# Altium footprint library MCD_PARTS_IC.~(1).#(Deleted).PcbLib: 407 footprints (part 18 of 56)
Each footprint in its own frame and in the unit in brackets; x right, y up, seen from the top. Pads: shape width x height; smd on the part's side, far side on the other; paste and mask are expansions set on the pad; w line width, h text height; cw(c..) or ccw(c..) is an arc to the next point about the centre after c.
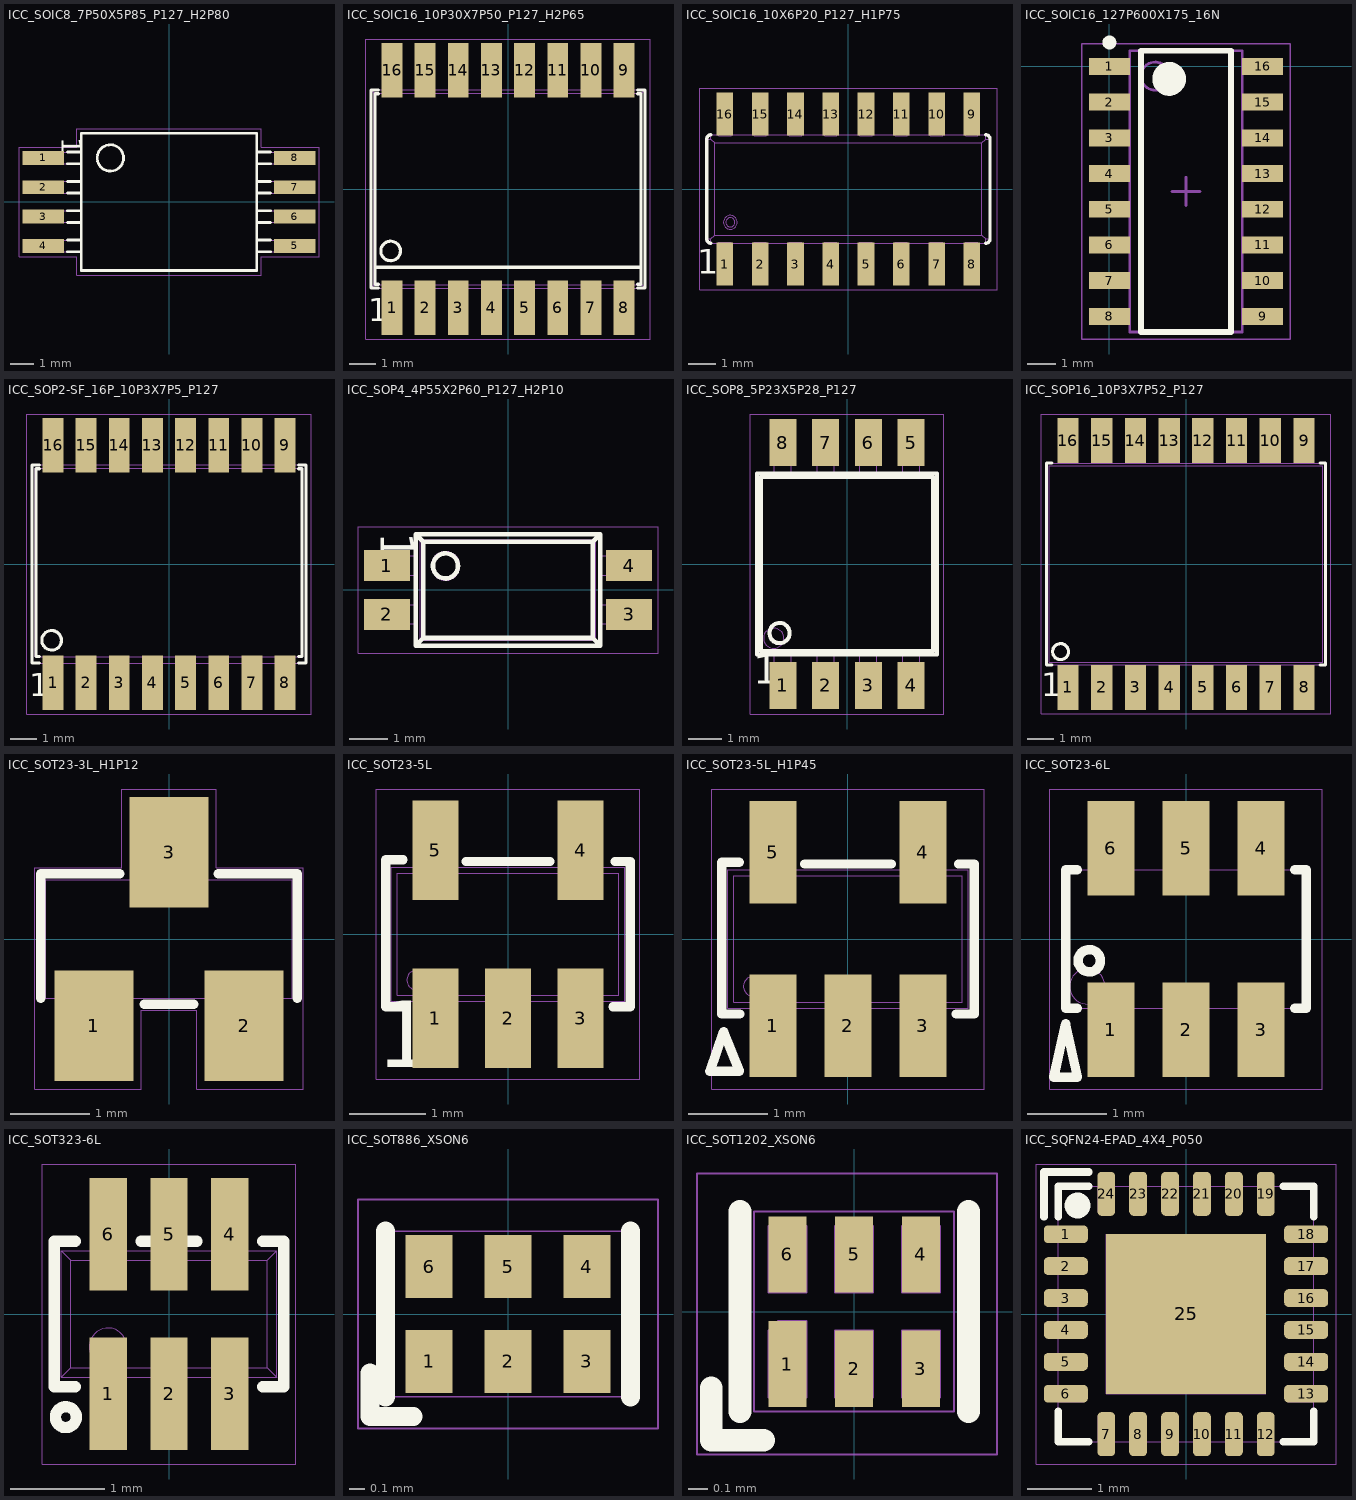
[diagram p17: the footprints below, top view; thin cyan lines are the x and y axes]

## ICC_SOIC8_7P50X5P85_P127_H2P80 [mm] "MCD-02031"
height 2.8
pads (8):
  rect 1.8x0.6 smd mask+0.05: 1(-5.45,1.905) 2(-5.45,0.635) 3(-5.45,-0.635) 4(-5.45,-1.905) 5(5.45,-1.905) 6(5.45,-0.635) 7(5.45,0.635) 8(5.45,1.905)
Top Overlay:
  circle w0.12: c-2.54,1.905 r0.572
  lines w0.12: -4.4,-2.159 -3.8,-2.159 ; -4.4,-1.651 -3.8,-1.651 ; -4.4,-0.889 -3.8,-0.889 ; -4.4,-0.381 -3.8,-0.381 ; -4.4,0.381 -3.8,0.381 ; -4.4,0.889 -3.8,0.889 ; -4.4,1.651 -3.8,1.651 ; -4.4,2.159 -3.8,2.159 ; 3.8,-2.159 4.4,-2.159 ; 3.8,-1.651 4.4,-1.651 ; 3.8,-0.889 4.4,-0.889 ; 3.8,-0.381 4.4,-0.381 ; 3.8,0.381 4.4,0.381 ; 3.8,0.889 4.4,0.889 ; 3.8,1.651 4.4,1.651 ; 3.8,2.159 4.4,2.159 ; -3.8,-2.975 -3.8,2.975 3.8,2.975 3.8,-2.975 -3.8,-2.975
  text "1" at -4.953,2.794 h1.5
M14-Top Assembly:
  circle w0.01: c-2.54,1.905 r0.572
  lines w0.01: -4.801,-2.159 -4.801,-1.651 ; -4.801,-0.889 -4.801,-0.381 ; -4.801,0.381 -4.801,0.889 ; -4.801,1.651 -4.801,2.159 ; -3.8,-2.159 -5.875,-2.159 -5.875,-1.651 -3.8,-1.651 ; -3.8,-0.889 -5.875,-0.889 -5.875,-0.381 -3.8,-0.381 ; -3.8,0.381 -5.875,0.381 -5.875,0.889 -3.8,0.889 ; -3.8,1.651 -5.875,1.651 -5.875,2.159 -3.8,2.159 ; 3.8,-2.159 5.875,-2.159 5.875,-1.651 3.8,-1.651 ; 3.8,-0.889 5.875,-0.889 5.875,-0.381 3.8,-0.381 ; 3.8,0.381 5.875,0.381 5.875,0.889 3.8,0.889 ; 3.8,1.651 5.875,1.651 5.875,2.159 3.8,2.159 ; 4.801,-2.159 4.801,-1.651 ; 4.801,-0.889 4.801,-0.381 ; 4.801,0.381 4.801,0.889 ; 4.801,1.651 4.801,2.159 ; -3.8,-2.975 3.8,-2.975 3.8,2.975 -3.8,2.975 -3.8,-2.975
  text "1" at -5.45,1.655 h0.75
  text "4" at -5.475,-2.145 h0.75
  text "5" at 5.149,-2.132 h0.75
  text "8" at 5.149,1.668 h0.75
  text "'.Designator'" at -2,-0.5 h0.75
M16-Top Courtyard:
  lines w0.01: -6.5,-2.375 -6.5,2.375 -4,2.375 -4,3.175 -3.8,3.175 4,3.175 4,2.375 6.5,2.375 6.5,-2.375 4,-2.375 4,-3.175 -4,-3.175 -4,-2.375 -6.5,-2.375
3D body: height 2.81, standoff 2.8, extent -3.046,1.401 -2.05,2.399
3D body: height 2.8, standoff 0, extent -3.8,-2.975 3.8,2.975
3D body: height 1.65, standoff 1.4, extent -5.05,1.651 -3.8,2.159
3D body: height 0.25, standoff 0, extent -5.875,1.651 -4.801,2.159
3D body: height 1.65, standoff 0, extent -5.05,1.651 -4.801,2.159
3D body: height 1.65, standoff 0, extent -5.05,0.381 -4.801,0.889
3D body: height 0.25, standoff 0, extent -5.875,0.381 -4.801,0.889
3D body: height 1.65, standoff 1.4, extent -5.05,0.381 -3.8,0.889
3D body: height 1.65, standoff 0, extent -5.05,-0.889 -4.801,-0.381
3D body: height 0.25, standoff 0, extent -5.875,-0.889 -4.801,-0.381
3D body: height 1.65, standoff 1.4, extent -5.05,-0.889 -3.8,-0.381
3D body: height 1.65, standoff 0, extent -5.05,-2.159 -4.801,-1.651
3D body: height 0.25, standoff 0, extent -5.875,-2.159 -4.801,-1.651
3D body: height 1.65, standoff 1.4, extent -5.05,-2.159 -3.8,-1.651
3D body: height 1.65, standoff 0, extent 4.801,-2.159 5.05,-1.651
3D body: height 0.25, standoff 0, extent 4.801,-2.159 5.875,-1.651
3D body: height 1.65, standoff 1.4, extent 3.8,-2.159 5.05,-1.651
3D body: height 1.65, standoff 0, extent 4.801,-0.889 5.05,-0.381
3D body: height 0.25, standoff 0, extent 4.801,-0.889 5.875,-0.381
3D body: height 1.65, standoff 1.4, extent 3.8,-0.889 5.05,-0.381
3D body: height 1.65, standoff 0, extent 4.801,0.381 5.05,0.889
3D body: height 0.25, standoff 0, extent 4.801,0.381 5.875,0.889
3D body: height 1.65, standoff 1.4, extent 3.8,0.381 5.05,0.889
3D body: height 1.65, standoff 0, extent 4.801,1.651 5.05,2.159
3D body: height 0.25, standoff 0, extent 4.801,1.651 5.875,2.159
3D body: height 1.65, standoff 1.4, extent 3.8,1.651 5.05,2.159

## ICC_SOIC16_10P30X7P50_P127_H2P65 [mm] "MCD-02008"
height 2.65
pads (16):
  rect 0.8x2.1 smd mask+0.05: 1(-4.445,-4.55) 2(-3.175,-4.55) 3(-1.905,-4.55) 4(-0.635,-4.55) 5(0.635,-4.55) 6(1.905,-4.55) 7(3.175,-4.55) 8(4.445,-4.55) 9(4.445,4.55) 10(3.175,4.55) 11(1.905,4.55) 12(0.635,4.55) 13(-0.635,4.55) 14(-1.905,4.55) 15(-3.175,4.55) 16(-4.445,4.55)
Top Overlay:
  circle w0.12: c-4.5,-2.375 r0.375
  lines w0.12: -5.1,-3 5.1,-3 ; -4.975,-3.8 -5.25,-3.8 -5.25,3.8 -4.975,3.8 ; -4.975,-3.65 -5.1,-3.65 -5.1,3.65 -4.975,3.65 ; 4.975,-3.8 5.25,-3.8 5.25,3.8 4.975,3.8 ; 4.975,-3.65 5.1,-3.65 5.1,3.65 4.975,3.65
  text "1" at -5.35,-5.35 h1.5
M14-Top Assembly:
  circle w0.01: c-4.5,-2.375 r0.378
  lines w0.01: -5.125,-3 5.125,-3 ; -4.699,-4.45 -4.191,-4.45 ; -4.699,-4.15 -4.191,-4.15 ; -4.699,-3.8 -4.699,-5.35 -4.191,-5.35 -4.191,-3.8 ; -4.699,3.8 -4.699,5.35 -4.191,5.35 -4.191,3.8 ; -4.699,4.15 -4.191,4.15 ; -4.699,4.45 -4.191,4.45 ; -3.429,-4.45 -2.921,-4.45 ; -3.429,-4.15 -2.921,-4.15 ; -3.429,-3.8 -3.429,-5.35 -2.921,-5.35 -2.921,-3.8 ; -3.429,3.8 -3.429,5.35 -2.921,5.35 -2.921,3.8 ; -3.429,4.15 -2.921,4.15 ; -3.429,4.45 -2.921,4.45 ; -2.159,-4.45 -1.651,-4.45 ; -2.159,-4.15 -1.651,-4.15 ; -2.159,-3.8 -2.159,-5.35 -1.651,-5.35 -1.651,-3.8 ; -2.159,3.8 -2.159,5.35 -1.651,5.35 -1.651,3.8 ; -2.159,4.15 -1.651,4.15 ; -2.159,4.45 -1.651,4.45 ; -0.889,-4.45 -0.381,-4.45 ; -0.889,-4.15 -0.381,-4.15 ; -0.889,-3.8 -0.889,-5.35 -0.381,-5.35 -0.381,-3.8 ; -0.889,3.8 -0.889,5.35 -0.381,5.35 -0.381,3.8 ; -0.889,4.15 -0.381,4.15 ; -0.889,4.45 -0.381,4.45 ; 0.381,-4.45 0.889,-4.45 ; 0.381,-4.15 0.889,-4.15 ; 0.381,-3.8 0.381,-5.35 0.889,-5.35 0.889,-3.8 ; 0.381,3.8 0.381,5.35 0.889,5.35 0.889,3.8 ; 0.381,4.15 0.889,4.15 ; 0.381,4.45 0.889,4.45 ; 1.651,-4.45 2.159,-4.45 ; 1.651,-4.15 2.159,-4.15 ; 1.651,-3.8 1.651,-5.35 2.159,-5.35 2.159,-3.8 ; 1.651,3.8 1.651,5.35 2.159,5.35 2.159,3.8 ; 1.651,4.15 2.159,4.15 ; 1.651,4.45 2.159,4.45 ; 2.921,-4.45 3.429,-4.45 ; 2.921,-4.15 3.429,-4.15 ; 2.921,-3.8 2.921,-5.35 3.429,-5.35 3.429,-3.8 ; 2.921,3.8 2.921,5.35 3.429,5.35 3.429,3.8 ; 2.921,4.15 3.429,4.15 ; 2.921,4.45 3.429,4.45 ; 4.191,-4.45 4.699,-4.45 ; 4.191,-4.15 4.699,-4.15 ; 4.191,-3.8 4.191,-5.35 4.699,-5.35 4.699,-3.8 ; 4.191,3.8 4.191,5.35 4.699,5.35 4.699,3.8 ; 4.191,4.15 4.699,4.15 ; 4.191,4.45 4.699,4.45 ; -5.25,-3.8 5.25,-3.8 ; -5.25,-3.8 -5.25,3.8 ; -5.25,-3.8 -5.125,-3.675 ; -5.25,3.8 5.25,3.8 ; -5.25,3.8 -5.125,3.675 ; -5.125,-3.675 5.125,-3.675 ; -5.125,-3.675 -5.125,3.675 ; -5.125,-3.675 -5.125,-3.675 ; -5.125,3.675 5.125,3.675 ; -5.125,3.675 -5.125,3.675 ; 5.125,-3.675 5.125,3.675 ; 5.125,-3.675 5.125,-3.675 ; 5.125,-3.675 5.25,-3.8 ; 5.125,3.675 5.125,3.675 ; 5.125,3.675 5.25,3.8 ; 5.25,-3.8 5.25,3.8
  text "16" at -5.075,4.35 h1.5
  text "9" at 4.125,4.35 h1.5
  text "8" at 4.125,-5.3 h1.5
  text "1" at -4.65,-5.325 h1.5
  text "'.Designator'" at -2,-0.5 h0.75
M16-Top Courtyard:
  lines w0.01: -5.45,-5.75 -5.45,5.75 5.45,5.75 5.45,-5.75 -4.875,-5.75 -5.45,-5.75
3D body "SOIC16_Wide_JEDEC_MS-013AA.STEP": height 2.65, standoff 0, extent -5.25,-5.315 5.25,5.315
3D body: height 0.3, standoff 0, extent -4.699,4.15 -4.191,5.35
3D body: height 1.3, standoff 0.3, extent -4.699,4.15 -4.191,4.45
3D body: height 1.6, standoff 1.3, extent -4.699,3.8 -4.191,4.45
3D body: height 0.3, standoff 0, extent -3.429,4.15 -2.921,5.35
3D body: height 1.3, standoff 0.3, extent -3.429,4.15 -2.921,4.45
3D body: height 1.6, standoff 1.3, extent -3.429,3.8 -2.921,4.45
3D body: height 0.3, standoff 0, extent -2.159,4.15 -1.651,5.35
3D body: height 1.3, standoff 0.3, extent -2.159,4.15 -1.651,4.45
3D body: height 1.6, standoff 1.3, extent -2.159,3.8 -1.651,4.45
3D body: height 0.3, standoff 0, extent -0.889,4.15 -0.381,5.35
3D body: height 1.3, standoff 0.3, extent -0.889,4.15 -0.381,4.45
3D body: height 1.6, standoff 1.3, extent -0.889,3.8 -0.381,4.45
3D body: height 0.3, standoff 0, extent 0.381,4.15 0.889,5.35
3D body: height 1.3, standoff 0.3, extent 0.381,4.15 0.889,4.45
3D body: height 1.6, standoff 1.3, extent 0.381,3.8 0.889,4.45
3D body: height 0.3, standoff 0, extent 1.651,4.15 2.159,5.35
3D body: height 1.3, standoff 0.3, extent 1.651,4.15 2.159,4.45
3D body: height 1.6, standoff 1.3, extent 1.651,3.8 2.159,4.45
3D body: height 0.3, standoff 0, extent 2.921,4.15 3.429,5.35
3D body: height 1.3, standoff 0.3, extent 2.921,4.15 3.429,4.45
3D body: height 1.6, standoff 1.3, extent 2.921,3.8 3.429,4.45
3D body: height 0.3, standoff 0, extent 4.191,4.15 4.699,5.35
3D body: height 1.3, standoff 0.3, extent 4.191,4.15 4.699,4.45
3D body: height 1.6, standoff 1.3, extent 4.191,3.8 4.699,4.45
3D body: height 0.3, standoff 0, extent 4.191,-5.35 4.699,-4.15
3D body: height 1.3, standoff 0.3, extent 4.191,-4.45 4.699,-4.15
3D body: height 1.6, standoff 1.3, extent 4.191,-4.45 4.699,-3.8
3D body: height 0.3, standoff 0, extent 2.921,-5.35 3.429,-4.15
3D body: height 1.3, standoff 0.3, extent 2.921,-4.45 3.429,-4.15
3D body: height 1.6, standoff 1.3, extent 2.921,-4.45 3.429,-3.8
3D body: height 0.3, standoff 0, extent 1.651,-5.35 2.159,-4.15
3D body: height 1.3, standoff 0.3, extent 1.651,-4.45 2.159,-4.15
3D body: height 1.6, standoff 1.3, extent 1.651,-4.45 2.159,-3.8
3D body: height 0.3, standoff 0, extent 0.381,-5.35 0.889,-4.15
3D body: height 1.3, standoff 0.3, extent 0.381,-4.45 0.889,-4.15
3D body: height 1.6, standoff 1.3, extent 0.381,-4.45 0.889,-3.8
3D body: height 0.3, standoff 0, extent -0.889,-5.35 -0.381,-4.15
3D body: height 1.3, standoff 0.3, extent -0.889,-4.45 -0.381,-4.15
3D body: height 1.6, standoff 1.3, extent -0.889,-4.45 -0.381,-3.8
3D body: height 0.3, standoff 0, extent -2.159,-5.35 -1.651,-4.15
3D body: height 1.3, standoff 0.3, extent -2.159,-4.45 -1.651,-4.15
3D body: height 1.6, standoff 1.3, extent -2.159,-4.45 -1.651,-3.8
3D body: height 0.3, standoff 0, extent -3.429,-5.35 -2.921,-4.15
3D body: height 1.3, standoff 0.3, extent -3.429,-4.45 -2.921,-4.15
3D body: height 1.6, standoff 1.3, extent -3.429,-4.45 -2.921,-3.8
3D body: height 1.6, standoff 1.3, extent -4.699,-4.45 -4.191,-3.8
3D body: height 1.3, standoff 0.3, extent -4.699,-4.45 -4.191,-4.15
3D body: height 0.3, standoff 0, extent -4.699,-5.35 -4.191,-4.15
3D body: height 2.65, standoff 0.2, extent -5.25,-3.8 5.25,3.8
3D body: height 2.66, standoff 2.65, extent -4.773,-3.224 -4.175,-2.625

## ICC_SOIC16_10X6P20_P127_H1P75 [mm] "MCD-03098"
height 1.75
pads (16):
  rect 0.6x1.55 smd mask+0.05: 1(-4.445,-2.7) 2(-3.175,-2.7) 3(-1.905,-2.7) 4(-0.635,-2.7) 5(0.635,-2.7) 6(1.905,-2.7) 7(3.175,-2.7) 8(4.445,-2.7) 9(4.445,2.7) 10(3.175,2.7) 11(1.905,2.7) 12(0.635,2.7) 13(-0.635,2.7) 14(-1.905,2.7) 15(-3.175,2.7) 16(-4.445,2.7)
Top Overlay:
  lines w0.12: -4.95,-1.95 cw(c-4.95,-1.8) -5.1,-1.8 -5.1,1.8 cw(c-4.95,1.8) -4.95,1.95 ; 4.95,-1.95 ccw(c4.95,-1.8) 5.1,-1.8 5.1,1.8 ccw(c4.95,1.8) 4.95,1.95
  text "1" at -5.45,-3.344 h1.5
M14-Top Assembly:
  drawing of 298 lines, arcs and shapes, not listed
  text "'.Designator'" at -2,-0.5 h0.75
  text "1" at -4.575,-2.95 h1.5
  text "8" at 4.05,-2.95 h1.5
  text "9" at 4.05,2.025 h1.5
  text "16" at -4.95,2 h1.5
M16-Top Courtyard:
  lines w0.01: -5.35,-3.625 -5.35,3.625 5.35,3.625 5.35,-3.625 -5.35,-3.625
3D body "User Library-so16.STEP": height 1.7, standoff 0, extent -5.1,-3 5.1,3

## ICC_SOIC16_127P600X175_16N [mm] "SOIC, 16-Leads, Body 9.90x3.90mm, Pitch 1.27mm, IPC Medium Density"
height 1.75
pads (16):
  rect 1.45x0.6 smd: 1(0,0) 2(0,-1.27) 3(0,-2.54) 4(0,-3.81) 5(0,-5.08) 6(0,-6.35) 7(0,-7.62) 8(0,-8.89) 9(5.45,-8.89) 10(5.45,-7.62) 11(5.45,-6.35) 12(5.45,-5.08) 13(5.45,-3.81) 14(5.45,-2.54) 15(5.45,-1.27) 16(5.45,0)
Top Overlay:
  circle w0.6: c2.125,-0.445 r0.3
  circle w0.25: c0,0.85 r0.125
  lines w0.2: 1.125,-9.445 4.325,-9.445 4.325,0.555 1.125,0.555 1.125,-9.445
Top Assembly:
  circle w0.1: c1.625,-0.345 r0.5
  lines w0.1: 0.725,-9.445 4.725,-9.445 4.725,0.555 0.725,0.555 0.725,-9.445
Top Courtyard:
  lines w0.05: -0.975,-9.695 6.425,-9.695 6.425,0.805 -0.975,0.805 -0.975,-9.695
  lines w0.1: 2.225,-4.445 3.225,-4.445 ; 2.725,-4.945 2.725,-3.945
3D body "SOIC127P600X175-16N.step": height 1.75, standoff 0, extent -0.275,-9.445 5.725,0.555

## ICC_SOP2-SF_16P_10P3X7P5_P127 [mm]
height 2.65
pads (16):
  rect 0.8x2.1 smd mask+0.05: 1(-4.445,-4.55) 2(-3.175,-4.55) 3(-1.905,-4.55) 4(-0.635,-4.55) 5(0.635,-4.55) 6(1.905,-4.55) 7(3.175,-4.55) 8(4.445,-4.55) 9(4.445,4.55) 10(3.175,4.55) 11(1.905,4.55) 12(0.635,4.55) 13(-0.635,4.55) 14(-1.905,4.55) 15(-3.175,4.55) 16(-4.445,4.55)
Top Overlay:
  circle w0.12: c-4.5,-2.925 r0.375
  lines w0.12: -4.975,-3.8 -5.25,-3.8 -5.25,3.8 -4.975,3.8 ; -4.975,-3.55 -5.1,-3.55 -5.1,3.65 -4.975,3.65 ; 4.975,-3.8 5.25,-3.8 5.25,3.8 4.975,3.8 ; 4.975,-3.55 5.1,-3.55 5.1,3.65 4.975,3.65
  text "1" at -5.35,-5.35 h1.5
M14-Top Assembly:
  circle w0.01: c-4.5,-2.925 r0.378
  lines w0.01: -4.699,-4.45 -4.191,-4.45 ; -4.699,-4.15 -4.191,-4.15 ; -4.699,-3.8 -4.699,-5.35 -4.191,-5.35 -4.191,-3.8 ; -4.699,3.8 -4.699,5.35 -4.191,5.35 -4.191,3.8 ; -4.699,4.15 -4.191,4.15 ; -4.699,4.45 -4.191,4.45 ; -3.429,-4.45 -2.921,-4.45 ; -3.429,-4.15 -2.921,-4.15 ; -3.429,-3.8 -3.429,-5.35 -2.921,-5.35 -2.921,-3.8 ; -3.429,3.8 -3.429,5.35 -2.921,5.35 -2.921,3.8 ; -3.429,4.15 -2.921,4.15 ; -3.429,4.45 -2.921,4.45 ; -2.159,-4.45 -1.651,-4.45 ; -2.159,-4.15 -1.651,-4.15 ; -2.159,-3.8 -2.159,-5.35 -1.651,-5.35 -1.651,-3.8 ; -2.159,3.8 -2.159,5.35 -1.651,5.35 -1.651,3.8 ; -2.159,4.15 -1.651,4.15 ; -2.159,4.45 -1.651,4.45 ; -0.889,-4.45 -0.381,-4.45 ; -0.889,-4.15 -0.381,-4.15 ; -0.889,-3.8 -0.889,-5.35 -0.381,-5.35 -0.381,-3.8 ; -0.889,3.8 -0.889,5.35 -0.381,5.35 -0.381,3.8 ; -0.889,4.15 -0.381,4.15 ; -0.889,4.45 -0.381,4.45 ; 0.381,-4.45 0.889,-4.45 ; 0.381,-4.15 0.889,-4.15 ; 0.381,-3.8 0.381,-5.35 0.889,-5.35 0.889,-3.8 ; 0.381,3.8 0.381,5.35 0.889,5.35 0.889,3.8 ; 0.381,4.15 0.889,4.15 ; 0.381,4.45 0.889,4.45 ; 1.651,-4.45 2.159,-4.45 ; 1.651,-4.15 2.159,-4.15 ; 1.651,-3.8 1.651,-5.35 2.159,-5.35 2.159,-3.8 ; 1.651,3.8 1.651,5.35 2.159,5.35 2.159,3.8 ; 1.651,4.15 2.159,4.15 ; 1.651,4.45 2.159,4.45 ; 2.921,-4.45 3.429,-4.45 ; 2.921,-4.15 3.429,-4.15 ; 2.921,-3.8 2.921,-5.35 3.429,-5.35 3.429,-3.8 ; 2.921,3.8 2.921,5.35 3.429,5.35 3.429,3.8 ; 2.921,4.15 3.429,4.15 ; 2.921,4.45 3.429,4.45 ; 4.191,-4.45 4.699,-4.45 ; 4.191,-4.15 4.699,-4.15 ; 4.191,-3.8 4.191,-5.35 4.699,-5.35 4.699,-3.8 ; 4.191,3.8 4.191,5.35 4.699,5.35 4.699,3.8 ; 4.191,4.15 4.699,4.15 ; 4.191,4.45 4.699,4.45 ; -5.25,-3.8 5.25,-3.8 5.25,3.8 -5.25,3.8 -5.25,-3.8 ; -5.125,-3.55 5.125,-3.55 5.125,3.675 -5.125,3.675 -5.125,-3.55
  text "16" at -5.075,4.35 h1.5
  text "9" at 4.125,4.35 h1.5
  text "8" at 4.125,-5.3 h1.5
  text "1" at -4.65,-5.325 h1.5
  text "'.Designator'" at -2,-0.5 h0.75
M16-Top Courtyard:
  lines w0.01: -5.45,-5.75 -5.45,5.75 5.45,5.75 5.45,-5.75 -4.875,-5.75 -5.45,-5.75
3D body: height 0.3, standoff 0, extent -4.699,4.15 -4.191,5.35
3D body: height 1.3, standoff 0.3, extent -4.699,4.15 -4.191,4.45
3D body: height 1.6, standoff 1.3, extent -4.699,3.8 -4.191,4.45
3D body: height 0.3, standoff 0, extent -3.429,4.15 -2.921,5.35
3D body: height 1.3, standoff 0.3, extent -3.429,4.15 -2.921,4.45
3D body: height 1.6, standoff 1.3, extent -3.429,3.8 -2.921,4.45
3D body: height 0.3, standoff 0, extent -2.159,4.15 -1.651,5.35
3D body: height 1.3, standoff 0.3, extent -2.159,4.15 -1.651,4.45
3D body: height 1.6, standoff 1.3, extent -2.159,3.8 -1.651,4.45
3D body: height 0.3, standoff 0, extent -0.889,4.15 -0.381,5.35
3D body: height 1.3, standoff 0.3, extent -0.889,4.15 -0.381,4.45
3D body: height 1.6, standoff 1.3, extent -0.889,3.8 -0.381,4.45
3D body: height 0.3, standoff 0, extent 0.381,4.15 0.889,5.35
3D body: height 1.3, standoff 0.3, extent 0.381,4.15 0.889,4.45
3D body: height 1.6, standoff 1.3, extent 0.381,3.8 0.889,4.45
3D body: height 0.3, standoff 0, extent 1.651,4.15 2.159,5.35
3D body: height 1.3, standoff 0.3, extent 1.651,4.15 2.159,4.45
3D body: height 1.6, standoff 1.3, extent 1.651,3.8 2.159,4.45
3D body: height 0.3, standoff 0, extent 2.921,4.15 3.429,5.35
3D body: height 1.3, standoff 0.3, extent 2.921,4.15 3.429,4.45
3D body: height 1.6, standoff 1.3, extent 2.921,3.8 3.429,4.45
3D body: height 0.3, standoff 0, extent 4.191,4.15 4.699,5.35
3D body: height 1.3, standoff 0.3, extent 4.191,4.15 4.699,4.45
3D body: height 1.6, standoff 1.3, extent 4.191,3.8 4.699,4.45
3D body: height 0.3, standoff 0, extent 4.191,-5.35 4.699,-4.15
3D body: height 1.3, standoff 0.3, extent 4.191,-4.45 4.699,-4.15
3D body: height 1.6, standoff 1.3, extent 4.191,-4.45 4.699,-3.8
3D body: height 0.3, standoff 0, extent 2.921,-5.35 3.429,-4.15
3D body: height 1.3, standoff 0.3, extent 2.921,-4.45 3.429,-4.15
3D body: height 1.6, standoff 1.3, extent 2.921,-4.45 3.429,-3.8
3D body: height 0.3, standoff 0, extent 1.651,-5.35 2.159,-4.15
3D body: height 1.3, standoff 0.3, extent 1.651,-4.45 2.159,-4.15
3D body: height 1.6, standoff 1.3, extent 1.651,-4.45 2.159,-3.8
3D body: height 0.3, standoff 0, extent 0.381,-5.35 0.889,-4.15
3D body: height 1.3, standoff 0.3, extent 0.381,-4.45 0.889,-4.15
3D body: height 1.6, standoff 1.3, extent 0.381,-4.45 0.889,-3.8
3D body: height 0.3, standoff 0, extent -0.889,-5.35 -0.381,-4.15
3D body: height 1.3, standoff 0.3, extent -0.889,-4.45 -0.381,-4.15
3D body: height 1.6, standoff 1.3, extent -0.889,-4.45 -0.381,-3.8
3D body: height 0.3, standoff 0, extent -2.159,-5.35 -1.651,-4.15
3D body: height 1.3, standoff 0.3, extent -2.159,-4.45 -1.651,-4.15
3D body: height 1.6, standoff 1.3, extent -2.159,-4.45 -1.651,-3.8
3D body: height 0.3, standoff 0, extent -3.429,-5.35 -2.921,-4.15
3D body: height 1.3, standoff 0.3, extent -3.429,-4.45 -2.921,-4.15
3D body: height 1.6, standoff 1.3, extent -3.429,-4.45 -2.921,-3.8
3D body: height 1.6, standoff 1.3, extent -4.699,-4.45 -4.191,-3.8
3D body: height 1.3, standoff 0.3, extent -4.699,-4.45 -4.191,-4.15
3D body: height 0.3, standoff 0, extent -4.699,-5.35 -4.191,-4.15
3D body: height 2.65, standoff 0.2, extent -5.25,-3.8 5.25,3.8
3D body: height 2.66, standoff 2.65, extent -4.772,-3.224 -4.175,-2.625

## ICC_SOP4_4P55X2P60_P127_H2P10 [mm] "MCD-02010"
height 2.2
pads (4):
  rect 1.2x0.8 smd mask+0.05: 1(-3.15,0.635) 2(-3.15,-0.635) 3(3.15,-0.635) 4(3.15,0.635)
Top Overlay:
  circle w0.12: c-1.625,0.625 r0.326
  lines w0.12: -2.4,-1.45 -2.4,1.45 ; -2.4,-1.45 2.4,-1.45 ; -2.4,-1.45 -2.2,-1.25 ; -2.4,1.45 2.4,1.45 ; -2.4,1.45 -2.2,1.25 ; -2.2,-1.25 2.2,-1.25 ; -2.2,-1.25 -2.2,1.25 ; -2.2,1.25 2.2,1.25 ; 2.2,-1.25 2.2,1.25 ; 2.2,-1.25 2.4,-1.45 ; 2.2,1.25 2.4,1.45 ; 2.4,-1.45 2.4,1.45
  text "1" at -3.6,1.5 h1.5
M14-Top Assembly:
  circle w0.01: c-1.625,0.625 r0.375
  lines w0.01: -2.9,-0.885 -2.9,-0.385 ; -2.9,0.385 -2.9,0.885 ; -2.7,-0.885 -2.7,-0.385 ; -2.7,0.385 -2.7,0.885 ; -2.4,-0.885 -3.7,-0.885 -3.7,-0.385 -2.4,-0.385 ; -2.4,0.385 -3.7,0.385 -3.7,0.885 -2.4,0.885 ; 2.4,-0.885 3.7,-0.885 3.7,-0.385 2.4,-0.385 ; 2.4,0.385 3.7,0.385 3.7,0.885 2.4,0.885 ; 2.7,-0.885 2.7,-0.385 ; 2.7,0.385 2.7,0.885 ; 2.9,-0.885 2.9,-0.385 ; 2.9,0.385 2.9,0.885 ; -2.4,-1.45 -2.28,-1.305 ; -2.4,-1.45 -2.4,1.45 ; -2.4,-1.45 2.4,-1.45 ; -2.4,1.45 -2.28,1.305 ; -2.4,1.45 2.4,1.45 ; -2.28,-1.305 2.28,-1.305 ; -2.28,-1.305 -2.28,1.305 ; -2.28,1.305 2.28,1.305 ; 2.28,-1.305 2.4,-1.45 ; 2.28,-1.305 2.28,1.305 ; 2.28,1.305 2.4,1.45 ; 2.4,-1.45 2.4,1.45
  text "4" at 3.105,0.395 h0.75
  text "3" at 3.155,-0.875 h0.75
  text "2" at -3.45,-0.875 h0.75
  text "1" at -3.41,0.395 h0.75
  text "'.Designator'" at -2,-0.5 h0.75
M16-Top Courtyard:
  lines w0.01: -3.9,-1.65 -3.9,1.65 3.9,1.65 3.9,-1.65 -3.9,-1.65
3D body "SOP-4-1.STEP": height 2.1, standoff 0, extent -3.5,-1.4 3.5,1.4
3D body: height 2.2, standoff 0, extent -2.4,-1.45 2.4,1.45

## ICC_SOP8_5P23X5P28_P127 [mm]
height 2.16
pads (8):
  rect 0.8x1.4 smd mask+0.05: 1(-1.905,-3.6) 2(-0.635,-3.6) 3(0.635,-3.6) 4(1.905,-3.6) 5(1.905,3.6) 6(0.635,3.6) 7(-0.635,3.6) 8(-1.905,3.6)
Top Overlay:
  circle w0.12: c-2,-2.05 r0.3
  lines w0.12: -2.665,-2.69 -2.665,2.69 2.665,2.69 2.665,-2.69 -2.665,-2.69 ; -2.55,-2.575 2.55,-2.575 2.55,2.575 -2.55,2.575 -2.55,-2.575
  text "1" at -2.775,-3.85 h1.5
M14-Top Assembly:
  circle w0.01: c-2.175,-2.2 r0.3
  lines w0.01: -2.155,-3.05 -1.655,-3.05 ; -2.155,-2.69 -2.155,-4.05 -1.655,-4.05 -1.655,-2.69 ; -2.155,2.69 -2.155,4.05 -1.655,4.05 -1.655,2.69 ; -2.155,3.05 -1.655,3.05 ; -0.885,-3.05 -0.385,-3.05 ; -0.885,-2.69 -0.885,-4.05 -0.385,-4.05 -0.385,-2.69 ; -0.885,2.69 -0.885,4.05 -0.385,4.05 -0.385,2.69 ; -0.885,3.05 -0.385,3.05 ; 0.385,-3.05 0.885,-3.05 ; 0.385,-2.69 0.385,-4.05 0.885,-4.05 0.885,-2.69 ; 0.385,2.69 0.385,4.05 0.885,4.05 0.885,2.69 ; 0.385,3.05 0.885,3.05 ; 1.655,-3.05 2.155,-3.05 ; 1.655,-2.69 1.655,-4.05 2.155,-4.05 2.155,-2.69 ; 1.655,2.69 1.655,4.05 2.155,4.05 2.155,2.69 ; 1.655,3.05 2.155,3.05 ; -2.665,-2.69 2.665,-2.69 2.665,2.69 -2.665,2.69 -2.665,-2.69 ; -2.55,-2.575 -2.55,2.575 2.55,2.575 2.55,-2.575 -2.55,-2.575
  text "'.Designator'" at -2,-0.5 h0.75
  text "8" at -2.225,3.08 h1.5
  text "5" at 1.6,3.08 h1.5
  text "4" at 1.575,-4.03 h1.5
  text "1" at -2.1,-4.03 h1.5
M16-Top Courtyard:
  lines w0.01: -2.875,-4.45 2.875,-4.45 2.875,4.45 -2.875,4.45 -2.875,2.7 -2.875,-4.45
3D body: height 2.16, standoff 0, extent -2.665,-2.69 2.665,2.69
3D body: height 0.25, standoff 0, extent -2.155,3.05 -1.655,4.05
3D body: height 1.2, standoff 0.25, extent -2.15,3.05 -1.65,3.3
3D body: height 1.2, standoff 0.95, extent -2.155,2.69 -1.655,3.05
3D body: height 2.17, standoff 2.16, extent -2.423,-2.449 -1.925,-1.95
3D body: height 1.2, standoff 0.95, extent -0.885,2.69 -0.385,3.05
3D body: height 1.2, standoff 0.25, extent -0.88,3.05 -0.38,3.3
3D body: height 0.25, standoff 0, extent -0.885,3.05 -0.385,4.05
3D body: height 1.2, standoff 0.95, extent 0.385,2.69 0.885,3.05
3D body: height 1.2, standoff 0.25, extent 0.39,3.05 0.89,3.3
3D body: height 0.25, standoff 0, extent 0.385,3.05 0.885,4.05
3D body: height 1.2, standoff 0.95, extent 1.655,2.69 2.155,3.05
3D body: height 1.2, standoff 0.25, extent 1.66,3.05 2.16,3.3
3D body: height 0.25, standoff 0, extent 1.655,3.05 2.155,4.05
3D body: height 1.2, standoff 0.95, extent 1.655,-3.05 2.155,-2.69
3D body: height 1.2, standoff 0.25, extent 1.65,-3.3 2.15,-3.05
3D body: height 0.25, standoff 0, extent 1.655,-4.05 2.155,-3.05
3D body: height 1.2, standoff 0.95, extent 0.385,-3.05 0.885,-2.69
3D body: height 1.2, standoff 0.25, extent 0.38,-3.3 0.88,-3.05
3D body: height 0.25, standoff 0, extent 0.385,-4.05 0.885,-3.05
3D body: height 1.2, standoff 0.95, extent -0.885,-3.05 -0.385,-2.69
3D body: height 1.2, standoff 0.25, extent -0.89,-3.3 -0.39,-3.05
3D body: height 0.25, standoff 0, extent -0.885,-4.05 -0.385,-3.05
3D body: height 1.2, standoff 0.95, extent -2.155,-3.05 -1.655,-2.69
3D body: height 1.2, standoff 0.25, extent -2.16,-3.3 -1.66,-3.05
3D body: height 0.25, standoff 0, extent -2.155,-4.05 -1.655,-3.05

## ICC_SOP16_10P3X7P52_P127 [mm] "MCD-02376"
height 2.65
pads (16):
  rect 0.8x1.7 smd mask+0.05: 1(-4.445,-4.65) 2(-3.175,-4.65) 3(-1.905,-4.65) 4(-0.635,-4.65) 5(0.635,-4.65) 6(1.905,-4.65) 7(3.175,-4.65) 8(4.445,-4.65) 9(4.445,4.65) 10(3.175,4.65) 11(1.905,4.65) 12(0.635,4.65) 13(-0.635,4.65) 14(-1.905,4.65) 15(-3.175,4.65) 16(-4.445,4.65)
Top Overlay:
  circle w0.12: c-4.725,-3.3 r0.3
  lines w0.12: -5.05,-3.8 -5.25,-3.8 -5.25,3.8 -5.05,3.8 ; 5.05,-3.8 5.25,-3.8 5.25,3.8 5.05,3.8
  text "1" at -5.45,-5.275 h1.5
M14-Top Assembly:
  circle w0.01: c-4.725,-3.3 r0.3
  lines w0.01: -4.695,-3.95 -4.195,-3.95 ; -4.695,-3.8 -4.695,-5.25 -4.195,-5.25 -4.195,-3.8 ; -4.695,3.8 -4.695,5.25 -4.195,5.25 -4.195,3.8 ; -4.695,3.95 -4.195,3.95 ; -3.425,-3.95 -2.925,-3.95 ; -3.425,-3.8 -3.425,-5.25 -2.925,-5.25 -2.925,-3.8 ; -3.425,3.8 -3.425,5.25 -2.925,5.25 -2.925,3.8 ; -3.425,3.95 -2.925,3.95 ; -2.155,-3.95 -1.655,-3.95 ; -2.155,-3.8 -2.155,-5.25 -1.655,-5.25 -1.655,-3.8 ; -2.155,3.8 -2.155,5.25 -1.655,5.25 -1.655,3.8 ; -2.155,3.95 -1.655,3.95 ; -0.885,-3.95 -0.385,-3.95 ; -0.885,-3.8 -0.885,-5.25 -0.385,-5.25 -0.385,-3.8 ; -0.885,3.8 -0.885,5.25 -0.385,5.25 -0.385,3.8 ; -0.885,3.95 -0.385,3.95 ; 0.385,-3.95 0.885,-3.95 ; 0.385,-3.8 0.385,-5.25 0.885,-5.25 0.885,-3.8 ; 0.385,3.8 0.385,5.25 0.885,5.25 0.885,3.8 ; 0.385,3.95 0.885,3.95 ; 1.655,-3.95 2.155,-3.95 ; 1.655,-3.8 1.655,-5.25 2.155,-5.25 2.155,-3.8 ; 1.655,3.8 1.655,5.25 2.155,5.25 2.155,3.8 ; 1.655,3.95 2.155,3.95 ; 2.925,-3.95 3.425,-3.95 ; 2.925,-3.8 2.925,-5.25 3.425,-5.25 3.425,-3.8 ; 2.925,3.8 2.925,5.25 3.425,5.25 3.425,3.8 ; 2.925,3.95 3.425,3.95 ; 4.195,-3.95 4.695,-3.95 ; 4.195,-3.8 4.195,-5.25 4.695,-5.25 4.695,-3.8 ; 4.195,3.8 4.195,5.25 4.695,5.25 4.695,3.8 ; 4.195,3.95 4.695,3.95 ; -5.25,-3.8 -5.25,3.8 5.25,3.8 5.25,-3.8 -5.25,-3.8 ; -5.15,-3.7 5.15,-3.7 5.15,3.7 -5.15,3.7 -5.15,-3.7
  text "1" at -4.7,-5.225 h1.5
  text "8" at 4.075,-5.25 h1.5
  text "9" at 4.125,4.25 h1.5
  text "16" at -5.1,4.225 h1.5
  text "'.Designator'" at -2,-0.5 h0.75
M16-Top Courtyard:
  lines w0.01: -5.45,-5.65 -5.45,5.65 5.45,5.65 5.45,-5.65 -5.45,-5.65
3D body "User Library-SOIC-16-300.STEP": height 2.58, standoff -0.02, extent -5.25,-5.3 5.25,5.3

## ICC_SOT23-3L_H1P12 [mm]
height 1.12
pads (3):
  rect 1x1.4 smd mask+0.05: 1(-0.95,-1.1) 2(0.95,-1.1) 3(0,1.1)
Top Overlay:
  lines w0.12: -1.625,-0.75 -1.625,0.825 -0.624,0.825 ; -0.312,-0.825 0.312,-0.825 ; 0.624,0.825 1.625,0.825 1.625,-0.75
M14-Top Assembly:
  lines w0.01: -1.56,-0.75 1.56,-0.75 1.56,0.75 -1.56,0.75 -1.56,-0.75 ; -1.275,-1.025 -1.275,-0.75 -0.675,-0.75 -0.675,-1.025 -1.275,-1.025 ; -0.25,0.75 -0.25,1.05 0.325,1.05 0.325,0.75 -0.25,0.75 ; 0.65,-1.025 0.65,-0.75 1.25,-0.75 1.25,-1.025 0.65,-1.025
  text "'.Designator'" at -2,-0.5 h0.75
M16-Top Courtyard:
  lines w0.01: -1.7,-1.9 -1.7,0.9 -0.6,0.9 -0.6,1.9 0.6,1.9 0.6,0.9 1.7,0.9 1.7,-1.9 0.35,-1.9 0.35,-0.9 -0.35,-0.9 -0.35,-1.9 -1.7,-1.9
3D body "SOT23-3_TO-236AB.STEP": height 1.09, standoff 0, extent -1.5,-1.25 1.5,1.25
3D body: height 1.12, standoff 0, extent -1.559,-0.749 1.559,0.749

## ICC_SOT23-5L [mm] "MCD-03445"
height 1.45
pads (5):
  rect 0.6x1.3 smd mask+0.05: 1(-0.95,-1.1) 2(0,-1.1) 3(0.95,-1.1) 4(0.95,1.1) 5(-0.95,1.1)
Top Overlay:
  lines w0.12: -1.375,0.975 -1.6,0.975 -1.6,-0.95 -1.372,-0.95 ; -0.55,0.95 0.55,0.95 ; 1.372,-0.95 1.6,-0.95 1.6,0.95 1.4,0.95
  text "1" at -1.725,-2.025 h1.5
M14-Top Assembly:
  circle w0.01: c-1.2,-0.6 r0.125
  lines w0.01: -1.15,-0.875 -1.15,-1.5 -0.75,-1.5 -0.75,-0.875 ; -1.15,0.875 -1.15,1.5 -0.75,1.5 -0.75,0.875 ; -0.2,-0.875 -0.2,-1.5 0.2,-1.5 0.2,-0.875 ; 0.75,-0.875 0.75,-1.5 1.15,-1.5 1.15,-0.875 ; 0.75,0.875 0.75,1.5 1.15,1.5 1.15,0.875 ; -1.525,-0.875 1.525,-0.875 1.525,0.875 -1.525,0.875 -1.525,-0.875 ; -1.45,-0.8 -1.45,0.8 1.45,0.8 1.45,-0.8 -1.45,-0.8
  text "'.Designator'" at 0,0 h0.75
M16-Top Courtyard:
  lines w0.01: -1.725,-1.9 1.725,-1.9 1.725,1.9 -1.725,1.9 -1.725,-1.9
3D body: height 1.45, standoff 0, extent -1.524,-0.874 1.524,0.874
3D body "SOT23-5L.STEP": height 1.1, standoff 0, extent -1.5,-1.25 1.5,1.25

## ICC_SOT23-5L_H1P45 [mm]
height 1.45
pads (5):
  rect 0.6x1.3 smd mask+0.05: 1(-0.95,-1.1) 2(0,-1.1) 3(0.95,-1.1) 4(0.95,1.1) 5(-0.95,1.1)
Top Overlay:
  lines w0.12: -1.375,0.975 -1.6,0.975 -1.6,-0.95 -1.372,-0.95 ; -0.55,0.95 0.55,0.95 ; 1.372,-0.95 1.6,-0.95 1.6,0.95 1.4,0.95 ; -1.75,-1.675 -1.575,-1.175 -1.375,-1.675 -1.75,-1.675
M14-Top Assembly:
  circle w0.01: c-1.2,-0.6 r0.125
  lines w0.01: -1.15,-0.875 -1.15,-1.5 -0.75,-1.5 -0.75,-0.875 ; -1.15,0.875 -1.15,1.5 -0.75,1.5 -0.75,0.875 ; -0.2,-0.875 -0.2,-1.5 0.2,-1.5 0.2,-0.875 ; 0.75,-0.875 0.75,-1.5 1.15,-1.5 1.15,-0.875 ; 0.75,0.875 0.75,1.5 1.15,1.5 1.15,0.875 ; -1.525,-0.875 -1.525,0.875 1.525,0.875 1.525,-0.875 -1.525,-0.875 ; -1.45,-0.8 1.45,-0.8 1.45,0.8 -1.45,0.8 -1.45,-0.8
  text "'.Designator'" at -2,-0.5 h0.75
M16-Top Courtyard:
  lines w0.01: -1.725,-1.9 -1.725,1.9 1.725,1.9 1.725,-1.9 -1.725,-1.9
3D body "SOT23-5L.STEP": height 1.1, standoff 0, extent -1.5,-1.25 1.5,1.25
3D body: height 1.45, standoff 0, extent -1.524,-0.874 1.524,0.874

## ICC_SOT23-6L [mm]
height 1.45
pads (6):
  rect 0.6x1.2 smd mask+0.05: 1(-0.95,-1.15) 2(0,-1.15) 3(0.95,-1.15) 4(0.95,1.15) 5(0,1.15) 6(-0.95,1.15)
Top Overlay:
  circle w0.12: c-1.225,-0.275 r0.141
  lines w0.12: -1.375,-0.875 -1.525,-0.875 -1.525,0.875 -1.375,0.875 ; 1.375,-0.875 1.525,-0.875 1.525,0.875 1.375,0.875 ; -1.675,-1.75 -1.525,-1.075 -1.375,-1.75 -1.675,-1.75
M14-Top Assembly:
  circle w0.01: c-1.25,-0.6 r0.224
  lines w0.01: -1.2,-0.875 -1.2,-1.5 -0.7,-1.5 -0.7,-0.875 ; -1.2,0.875 -1.2,1.5 -0.7,1.5 -0.7,0.875 ; -0.25,-0.875 -0.25,-1.5 0.25,-1.5 0.25,-0.875 ; -0.25,0.875 -0.25,1.5 0.25,1.5 0.25,0.875 ; 0.7,-0.875 0.7,-1.5 1.2,-1.5 1.2,-0.875 ; 0.7,0.875 0.7,1.5 1.2,1.5 1.2,0.875 ; -1.525,-0.875 -1.525,0.875 1.525,0.875 1.525,-0.875 -1.525,-0.875
  text "2" at -0.15,-1.425 h0.75
  text "3" at 0.78,-1.43 h0.75
  text "1" at -1.05,-1.425 h0.75
  text "6" at -1.1,0.925 h0.75
  text "5" at -0.15,0.925 h0.75
  text "4" at 0.78,0.91 h0.75
  text "'.Designator'" at -2,-0.5 h0.75
M16-Top Courtyard:
  lines w0.01: -1.725,-1.9 -1.725,1.9 1.725,1.9 1.725,-1.9 -1.725,-1.9
3D body "SOT23-6.STEP": height 1.3, standoff 0, extent -1.5,-1.5 1.5,1.5
3D body: height 1.45, standoff 0, extent -1.524,-0.874 1.524,0.874

## ICC_SOT323-6L [mm]
height 1.1
pads (6):
  rect 0.4x1.2 smd mask+0.05: 1(-0.65,-0.85) 2(0,-0.85) 3(0.65,-0.85) 4(0.65,0.85) 5(0,0.85) 6(-0.65,0.85)
Top Overlay:
  circle w0.12: c-1.1,-1.1 r0.112
  lines w0.12: -1,-0.775 -1.225,-0.775 -1.225,0.775 -1,0.775 ; -0.3,0.775 0.3,0.775 ; 1,-0.775 1.225,-0.775 1.225,0.775 1,0.775
M14-Top Assembly:
  circle w0.01: c-0.65,-0.35 r0.2
  lines w0.01: -0.75,-0.675 -0.75,-1.2 -0.55,-1.2 -0.55,-0.675 ; -0.75,0.675 -0.75,1.2 -0.55,1.2 -0.55,0.675 ; -0.1,-0.675 -0.1,-1.2 0.1,-1.2 0.1,-0.675 ; -0.1,0.675 -0.1,1.2 0.1,1.2 0.1,0.675 ; 0.55,-0.675 0.55,-1.2 0.75,-1.2 0.75,-0.675 ; 0.55,0.675 0.55,1.2 0.75,1.2 0.75,0.675 ; -1.15,-0.675 -1.05,-0.575 ; -1.15,-0.675 -1.15,0.675 ; -1.15,-0.675 1.15,-0.675 ; -1.15,0.675 -1.05,0.575 ; -1.15,0.675 1.15,0.675 ; -1.05,-0.575 -1.05,0.575 ; -1.05,-0.575 1.05,-0.575 ; -1.05,0.575 1.05,0.575 ; 1.05,-0.575 1.15,-0.675 ; 1.05,-0.575 1.05,0.575 ; 1.05,0.575 1.15,0.675 ; 1.15,-0.675 1.15,0.675
  text "'.Designator'" at 0,0 h0.75
M16-Top Courtyard:
  lines w0.01: -1.35,-1.6 1.35,-1.6 1.35,1.6 -1.35,1.6 -1.35,-1.6
3D body: height 1.1, standoff 0, extent -1.15,-0.675 1.15,0.675
3D body "SOT323-5L.STEP": height 1, standoff 0, extent -1.05,-1.051 1.05,1.051

## ICC_SOT886_XSON6 [mm] "MCD-01514"
height 0.5
pads (6):
  rect 0.3x0.4 smd mask+0.05: 1(-0.5,-0.3) 2(0,-0.3) 3(0.5,-0.3) 4(0.5,0.3) 5(0,0.3) 6(-0.5,0.3)
Top Overlay:
  lines w0.12: -0.875,-0.375 -0.875,-0.65 -0.6,-0.65 ; -0.775,-0.525 -0.775,0.525 ; 0.775,-0.525 0.775,0.525
M14-Top Assembly:
  lines w0.01: -0.75,-0.525 0.75,-0.525 0.75,0.525 -0.75,0.525 -0.75,-0.525 ; -0.625,-0.475 -0.375,-0.475 -0.375,-0.125 -0.625,-0.125 -0.625,-0.475 ; -0.625,0.125 -0.375,0.125 -0.375,0.475 -0.625,0.475 -0.625,0.125 ; -0.125,-0.475 0.125,-0.475 0.125,-0.125 -0.125,-0.125 -0.125,-0.475 ; -0.125,0.125 0.125,0.125 0.125,0.475 -0.125,0.475 -0.125,0.125 ; 0.375,-0.475 0.625,-0.475 0.625,-0.125 0.375,-0.125 0.375,-0.475 ; 0.375,0.125 0.625,0.125 0.625,0.475 0.375,0.475 0.375,0.125
  text "6" at -0.6,0.138 h0.5
  text "5" at -0.1,0.138 h0.5
  text "4" at 0.387,0.138 h0.5
  text "3" at 0.4,-0.463 h0.5
  text "2" at -0.112,-0.463 h0.5
  text "1" at -0.575,-0.463 h0.5
  text "'.Designator'" at -2,-0.5 h0.75
M16-Top Courtyard:
  lines w0.01: -0.95,-0.725 0.95,-0.725 0.95,0.725 -0.95,0.725 -0.95,-0.725
3D body: height 0.5, standoff 0, extent -0.75,-0.525 0.75,0.525
3D body: height 0.51, standoff 0.5, extent -0.675,-0.45 -0.425,-0.2
3D body "SOT886.STEP": height 0.48, standoff -0.02, extent -0.725,-0.5 0.725,0.5

## ICC_SOT1202_XSON6 [mm] "MCD-02753"
height 0.35
pads (6):
  rect 0.2x0.45 smd mask+0.038: 1(-0.35,-0.275)
  rect 0.2x0.4 smd mask+0.038: 2(0,-0.3) 3(0.35,-0.3) 4(0.35,0.3) 5(0,0.3) 6(-0.35,0.3)
Top Overlay:
  lines w0.12: -0.75,-0.4 -0.75,-0.675 -0.475,-0.675 ; -0.6,-0.525 -0.6,0.525 ; 0.6,-0.525 0.6,0.525
M14-Top Assembly:
  lines w0.01: -0.525,-0.525 -0.525,0.525 0.525,0.525 0.525,-0.525 -0.525,-0.525 ; -0.45,-0.45 -0.25,-0.45 -0.25,-0.05 -0.4,-0.05 -0.45,-0.1 -0.45,-0.45 ; -0.45,0.1 -0.45,0.45 -0.25,0.45 -0.25,0.1 -0.45,0.1 ; -0.1,-0.45 -0.1,-0.1 0.1,-0.1 0.1,-0.45 -0.1,-0.45 ; -0.1,0.1 -0.1,0.45 0.1,0.45 0.1,0.1 -0.1,0.1 ; 0.25,-0.45 0.25,-0.1 0.45,-0.1 0.45,-0.45 0.25,-0.45 ; 0.25,0.1 0.25,0.45 0.45,0.45 0.45,0.1 0.25,0.1
  text "1" at -0.425,-0.45 h0.5
  text "2" at -0.125,-0.45 h0.5
  text "3" at 0.225,-0.45 h0.5
  text "6" at -0.475,0.075 h0.5
  text "5" at -0.125,0.1 h0.5
  text "4" at 0.225,0.1 h0.5
  text "'.Designator'" at -2,-0.5 h0.75
M16-Top Courtyard:
  lines w0.01: -0.825,-0.75 -0.825,0.725 0.75,0.725 0.75,-0.75 -0.825,-0.75
3D body: height 0.51, standoff 0.5, extent -0.5,-0.425 -0.25,-0.175
3D body: height 0.5, standoff 0, extent -0.525,-0.525 0.525,0.525
3D body "User Library-SOT 1202.STEP": height 0.35, standoff -0.04, extent -0.5,-0.5 0.5,0.5

## ICC_SQFN24-EPAD_4X4_P050 [mm] "MCD-02348"
height 1
pads (25):
  rrect50% 0.69x0.28 smd mask+0.05: 1(-1.883,1.25) 2(-1.883,0.75) 3(-1.883,0.25) 4(-1.883,-0.25) 5(-1.883,-0.75) 6(-1.883,-1.25) 13(1.883,-1.25) 14(1.883,-0.75) 15(1.883,-0.25) 16(1.883,0.25) 17(1.883,0.75) 18(1.883,1.25)
  rrect50% 0.28x0.69 smd mask+0.05: 7(-1.25,-1.883) 8(-0.75,-1.883) 9(-0.25,-1.883) 10(0.25,-1.883) 11(0.75,-1.883) 12(1.25,-1.883) 19(1.25,1.883) 20(0.75,1.883) 21(0.25,1.883) 22(-0.25,1.883) 23(-0.75,1.883) 24(-1.25,1.883)
  rect 2.5x2.5 smd paste-10 mask+0.05: 25(0,0)
Top Overlay:
  circle w0.254: c-1.7,1.7 r0.075
  lines w0.12: -2.225,1.525 -2.225,2.225 -1.525,2.225 ; -2,-1.525 -2,-2 -1.525,-2 ; -2,1.525 -2,2 -1.525,2 ; 1.525,-2 2,-2 2,-1.525 ; 1.525,2 2,2 2,1.525
Top Paste:
  rectangle: -0.875,-0.875 -0.125,-0.125
  rectangle: 0.125,-0.875 0.875,-0.125
  rectangle: 0.125,0.125 0.875,0.875
  rectangle: -0.875,0.125 -0.125,0.875
M14-Top Assembly:
  lines w0.01: -2,-1.375 -1.6,-1.375 -1.6,-1.125 -2,-1.125 ; -2,-0.875 -1.6,-0.875 -1.6,-0.625 -2,-0.625 ; -2,-0.375 -1.6,-0.375 -1.6,-0.125 -2,-0.125 ; -2,0.125 -1.6,0.125 -1.6,0.375 -2,0.375 ; -2,0.625 -1.6,0.625 -1.6,0.875 -2,0.875 ; -2,1.125 -1.6,1.125 -1.6,1.375 -2,1.375 ; -1.375,-2 -1.375,-1.6 -1.125,-1.6 -1.125,-2 ; -1.375,2 -1.375,1.6 -1.125,1.6 -1.125,2 ; -0.875,-2 -0.875,-1.6 -0.625,-1.6 -0.625,-2 ; -0.875,2 -0.875,1.6 -0.625,1.6 -0.625,2 ; -0.375,-2 -0.375,-1.6 -0.125,-1.6 -0.125,-2 ; -0.375,2 -0.375,1.6 -0.125,1.6 -0.125,2 ; 0.125,-2 0.125,-1.6 0.375,-1.6 0.375,-2 ; 0.125,2 0.125,1.6 0.375,1.6 0.375,2 ; 0.625,-2 0.625,-1.6 0.875,-1.6 0.875,-2 ; 0.625,2 0.625,1.6 0.875,1.6 0.875,2 ; 1.125,-2 1.125,-1.6 1.375,-1.6 1.375,-2 ; 1.125,2 1.125,1.6 1.375,1.6 1.375,2 ; 2,-1.375 1.6,-1.375 1.6,-1.125 2,-1.125 ; 2,-0.875 1.6,-0.875 1.6,-0.625 2,-0.625 ; 2,-0.375 1.6,-0.375 1.6,-0.125 2,-0.125 ; 2,0.125 1.6,0.125 1.6,0.375 2,0.375 ; 2,0.625 1.6,0.625 1.6,0.875 2,0.875 ; 2,1.125 1.6,1.125 1.6,1.375 2,1.375 ; -2,-2 -2,2 2,2 2,-2 -2,-2 ; -1.25,-1.25 1.25,-1.25 1.25,1.25 -1.25,1.25 -1.25,-1.25
  text "'.Designator'" at -2,0.2 h0.75
  text "6" at -1.975,-1.15 h0.5
  text "24" at -1.525,1.65 h0.5
  text "19" at 1.025,1.65 h0.5
  text "18" at 1.975,1.025 h0.5
  text "13" at 1.975,-1.475 h0.5
  text "12" at 1.025,-1.975 h0.5
  text "7" at -1.35,-1.975 h0.5
  text "1" at -1.975,1.325 h0.5
  text "25" at -0.3,-0.225 h0.65
M16-Top Courtyard:
  lines w0.01: -2.35,-2.35 2.35,-2.35 2.35,2.35 -2.35,2.35 -2.35,-2.35
3D body "VQFN24-EPAD.STEP": height 1.05, standoff -0.03, extent -2.05,-2.05 2.05,2.05
3D body: height 1.1, standoff 1, extent -1.448,1.05 -1.05,1.45
3D body: height 1, standoff 0, extent -2,-2 2,2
